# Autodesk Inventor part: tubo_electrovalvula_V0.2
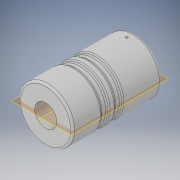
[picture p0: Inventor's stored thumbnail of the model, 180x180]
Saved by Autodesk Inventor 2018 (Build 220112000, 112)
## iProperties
Created: 2018-09
Part Number: tubo_electrovalvula_V0.2
Material: Generic
Document SubType Name: Modeling
Designer: Gordillo
Density: 1 g/cm^3
Appearance: Default
Author: Gordillo
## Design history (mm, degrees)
sketch "Sketch1"
  geometry: C1 r 55 at (0, 0); 1 further point
  constraints: 1 centre point, 1 coincident
  dimensions: "d0" = 110 diameter of C1
extrude "Extrusion1" new body sketch "Sketch1" distance "d1" = 180; taper "d2" = 0 deg
sketch "Sketch2"
  geometry: L1 (55, 180)-(-55, 180) reference; L2 (-55, 0)-(55, 0) reference; L3 (55, 0)-(55, 180) reference; L4 (55, 80)-(52, 80); L5 (52, 80)-(52, 92); L6 (52, 92)-(55, 92); L7 (55, 92)-(55, 80); L8 (55, 108)-(52, 108); L9 (52, 108)-(52, 120); L10 (52, 120)-(55, 120); L11 (55, 120)-(55, 108); L12 (0, -36)-(0, 216) reference; 1 further point
  constraints: 16 end point, 4 parallel, 2 horizontal, 2 perpendicular, 2 point on line
  dimensions: "d3" = 3 distance of L5.end L6.end; "d4" = 12 distance of L4.end L5.end; "d5" = 80 distance between parallel lines of L2 L4; "d6" = 3 distance of L9.end L10.end; "d7" = 12 distance of L8.end L9.end; "d8" = 16 distance between parallel lines of L8 L6
revolve "Revolution1" sketch "Sketch2" stored, may be unused: angle "d9" = 90 deg
fillet "Fillet1" dims "d10" = 4
sketch "Sketch3"
  geometry: C1 r 22.5 at (0, 0); 1 further point
  constraints: 1 centre point, 1 coincident
  dimensions: "d11" = 45 diameter of C1
extrude "Extrusion2" cut sketch "Sketch3" distance "d12" = 150; taper "d13" = 0 deg
fillet "Fillet2" dims "d14" = 4
workplane "Work Plane1"
sketch "Sketch4"
  geometry: L1 (0, -36)-(0, 216) reference; L2 (51, 0)-(-51, 0) reference; 2 further points
  constraints: 1 point on line
  dimensions: "d15" = 45 distance from line of L2 point (0, 45)
hole "Hole1" sketch "Sketch4" at (0, 45) diameter "d16" = 12; stored, may be unused: countersink angle "d20" = 90 deg, drill point angle "d22" = 118 deg; dims "d17" = 6, "d18" = 14, "d19" = 4, "d21" = 8
thread "Thread1" dims "d23" = 10, "d24" = 0
sketch "Sketch5"
  geometry: L1 (-55, 4)-(55, 4) reference; L2 (51, 0)-(-51, 0) reference; L3 (-55, 4)-(-55, 76.127) reference; L4 (55, 4)-(55, 76.127) reference; L5 (0, -36.994)-(0, 216.166) reference; C1 r 2 at (0, 15); A1 r 4 centre (51, 4) between (51, 0) and (55, 4) reference; A2 r 4 centre (-51, 4) between (-55, 4) and (-51, 0) reference; 1 further point
  constraints: 1 centre point, 1 point on line
  dimensions: "d25" = 4 diameter of C1; "d26" = 15 distance from line of L2 C1.centre
extrude "Extrusion3" cut sketch "Sketch5" extent not by distance; stored distance "d27" = 200; taper "d28" = 0 deg
body "Solid1"
node "Projected Loop1"
node "Projected Loop2"
